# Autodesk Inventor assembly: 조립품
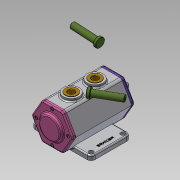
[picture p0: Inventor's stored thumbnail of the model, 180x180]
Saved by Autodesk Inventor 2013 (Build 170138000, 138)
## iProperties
Created: 2021-06
Part Number: 조립품
Document SubType Name: Assembly
Designer: max6
Author: max6
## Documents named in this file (11)
- C:\Users\max6\Desktop\710606V1025\조립품.iam
- C:\Users\max6\Desktop\710606V1025\본체.ipt
- C:\Users\max6\Desktop\710606V1025\앞커버.ipt
- C:\Users\max6\Desktop\710606V1025\뒷커버.ipt
- C:\Users\max6\Desktop\710606V1025\편심축.ipt
- C:\Users\max6\Desktop\710606V1025\베어링 6203.ipt
- C:\Users\max6\Desktop\710606V1025\베어링 6302.ipt
- C:\Users\max6\Desktop\710606V1025\오일실.ipt
- C:\Users\max6\Desktop\710606V1025\부시.ipt
- C:\Users\max6\Desktop\710606V1025\볼트 M4.ipt
- C:\Users\max6\Desktop\710606V1025\슬라이더.ipt
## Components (10 placed, 3 different names)
1. 7-베어링 6203:1
2. 8-오일실:1
3. 9-M4-소켓머리:1
4. 9-M4-소켓머리:2
5. 9-M4-소켓머리:3
6. 9-M4-소켓머리:4
7. 9-M4-소켓머리:5
8. 9-M4-소켓머리:6
9. 9-M4-소켓머리:7
10. 9-M4-소켓머리:8
